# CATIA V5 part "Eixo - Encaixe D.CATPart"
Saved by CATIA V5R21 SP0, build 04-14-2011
Part number: Eixo - Encaixe D
Definition: Eixo - Encaixe D
Nomenclature: Eixo - Encaixe D
Source: Unknown
Bounding box of the stored display mesh (mm): x -1.5 to 1.5, y -5.2 to 10.8, z -1.5 to 1.5
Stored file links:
  C:\Users\beatr\OneDrive\Documents\UNB\2026_1\Pi1\Componentes eletronicos\Eixo - Encaixe D.CATPart
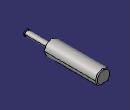
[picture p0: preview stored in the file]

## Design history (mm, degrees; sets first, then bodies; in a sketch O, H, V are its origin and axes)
Body1 "Sólido1" (main body)
  Solid1: solid without history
